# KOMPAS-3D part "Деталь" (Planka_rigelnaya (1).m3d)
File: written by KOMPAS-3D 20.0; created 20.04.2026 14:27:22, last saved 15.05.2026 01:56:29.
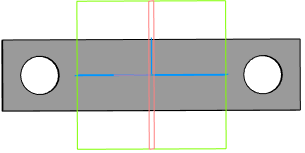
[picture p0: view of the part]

Document properties: Автор: TMK; Полное имя файла: E:\test_kompas\all_v18\Planka_rigelnaya (1).m3d; Организация: TMK

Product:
- Part/product: Деталь
    Масса: 0.134151
  - Body: Тело 1

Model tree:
1. Эскиз:1
2. Элемент выдавливания:1
     Расстояние 2 = 8
3. Эскиз:2
4. Элемент выдавливания:2
     Расстояние 2 = 10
